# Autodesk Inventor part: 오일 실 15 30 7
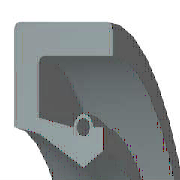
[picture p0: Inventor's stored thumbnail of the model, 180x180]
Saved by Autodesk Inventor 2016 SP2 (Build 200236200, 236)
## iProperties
IsCustomPart: 1
Created: 2012-02
Part Number: 오일 실 15 30 7
Material: 고무
Description: 오일-실
Document SubType Name: Modeling
Standard: KS B 2804
Designer: mduedu
Standards Organization: KS
Language: ko-KR
Size Designation: S - 15 30 7
Categories: <MemberInstance><Categories><Category DisplayName="샤프트 부품" InternalName="7f7aeb1f-a693-4053-b835-cee3144e0d98" Mnemonic="SHFT"><Category DisplayName="실링" Intern
Density: 0.93 g/cm^3
Appearance: 고무 - 검은색 - 버전 1.1
Author: mduedu
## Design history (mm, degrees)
revolve "본체" stored, may be unused: angle "d17" = 90 deg
revolve "스프링1" stored, may be unused: angle "d18" = 90 deg
body "Solid1"
sketch "스케치1"
  geometry: L1 (0, 15)-(7, 15); L2 (7, 15)-(7, 13.75); L3 (7, 13.75)-(1.75, 13.75); L4 (0, 15)-(0, 9.6); L5 (0, 9.6)-(1.75, 9.25); L6 (1.75, 9.25)-(4.9, 7.5); L7 (4.9, 7.5)-(0, 7.5); L8 (6.3, 8.375)-(6.3, 9.6); L9 (0, 0)-(9.586, 0) reference; L10 (4.9, 7.5)-(6.3, 8.375); L11 (0, 18)-(0, -3) reference; L12 (-1.917, 0)-(11.503, 0) reference; L13 (4.2, 9.6)-(1.75, 10.09); L14 (1.75, 10.09)-(1.75, 13.75); L15 (6.3, 9.6)-(5.6, 9.6); C1 r 0.455 at (4.9, 9.6); A1 r 0.7 centre (4.9, 9.6) between (5.6, 9.6) and (4.2, 9.6)
  constraints: 26 end point, 5 horizontal alignment, 4 perpendicular, 2 centre point, 2 collinear, 2 horizontal, 2 parallel, 2 point on circle, 2 point on line, 2 vertical alignment, 1 coincident
  dimensions: "d0" = 30 diameter of L1 L9 (= SD2); "d1" = 16.75 diameter of L8.start L9 (= ABDM); "d2" = 1.25 distance of L1.end L2.end (computed from SD); "d3" = 0.91 diameter of C1 (= SPDI); "d4" = 1.4 diameter of A1 (= SPDA); "d5" = 15 diameter of L6.end L9 (= NND); "d6" = 18.5 diameter of L5.end L9 (= TKDM); "d7" = 19.2 diameter of L4.end L9 (= HLDM); "d8" = 4.9 distance from line of C1.centre L4 (= SPDST); "d9" = 6.3 distance between parallel lines of L8 L4 (= SDI); "d10" = 7 distance between parallel lines of L2 L4 (= SWDT); "d12" = 1.75 distance between parallel lines of L14 L4 (= SD)
fillet "모깎기1" dims "d11" = 0.3 (= RR)
other parameters: "SD2" = 30 [user parameter; used in 1 equation term], "SWDT" = 7 [user parameter; used in 1 equation term], "RR" = 0.3 [user parameter; used in 1 equation term], "SD" = 1.75 [user parameter; used in 2 equation terms], "NND" = 15 [user parameter; used in 1 equation term], "SPDA" = 1.4 [user parameter; used in 1 equation term], "SPDI" = 0.91 [user parameter; used in 1 equation term], "TKDM" = 18.5 [user parameter; used in 1 equation term], "HLDM" = 19.2 [user parameter; used in 1 equation term], "ABDM" = 16.75 [user parameter; used in 1 equation term], "SDI" = 6.3 [user parameter; used in 1 equation term], "SPDST" = 4.9 [user parameter; used in 1 equation term], "d13" = 0, "d14" = 0, "d15" = 0, "LAB" = 0.35 [user parameter]
